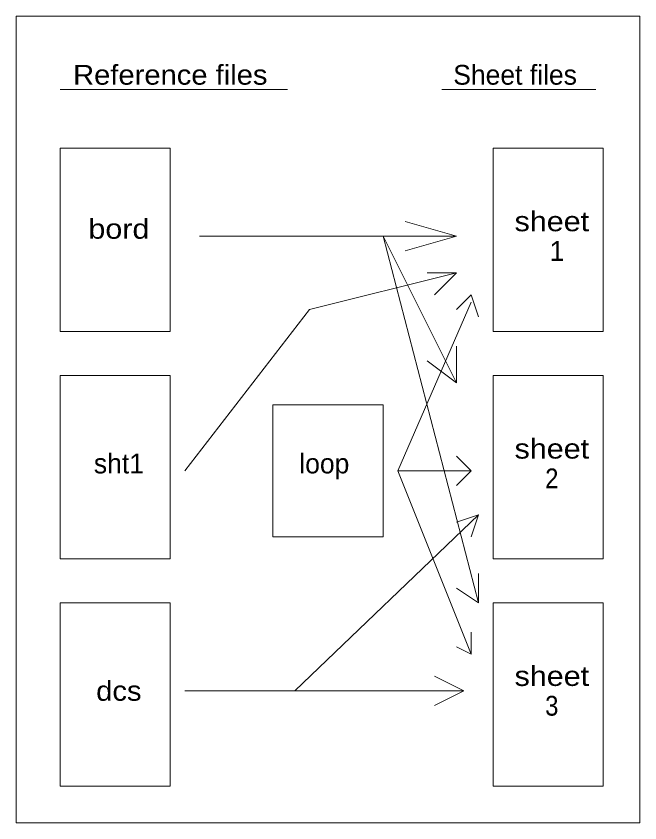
# Model space of a CAD drawing. Extents: x 0 to 0.708, y 0 to 0.917.
import ezdxf
from ezdxf.enums import TextEntityAlignment as Align

# ---------------------------------------------------------------- set-up
doc = ezdxf.new("R2010")
doc.units = 0
doc.header["$LTSCALE"] = 0.009
for name, color, linetype, lineweight in [('30', 7, 'Continuous', 13), ('31', 7, 'Continuous', 13), ('61', 7, 'Continuous', 13), ('62', 7, 'Continuous', 13)]:
    doc.layers.add(name, color=color, linetype=linetype, lineweight=lineweight)
doc.layers.add('5', color=7, linetype='Continuous')

msp = doc.modelspace()

# ---------------------------------------------------------------- linework, layer by layer
at = {"layer": '30'}
for p, q in [((0.416666, 0.666666), (0.5, 0.5)), ((0.416666, 0.666666), (0.525, 0.25)), ((0.433333, 0.4), (0.516666, 0.591666)), ((0.433333, 0.4), (0.516666, 0.4)), ((0.433333, 0.4), (0.516666, 0.191666)), ((0.316666, 0.15), (0.508333, 0.15))]:
    msp.add_line(p, q, dxfattribs=at)
for points in [[(0.208333, 0.666666), (0.416666, 0.666666), (0.5, 0.666666)], [(0.191666, 0.4), (0.333333, 0.583333), (0.5, 0.625)], [(0.191666, 0.15), (0.316666, 0.15), (0.525, 0.35)]]:
    msp.add_lwpolyline(points, dxfattribs=at)
at = {"layer": '31'}
for p, q in [((0.5, 0.666666), (0.441666, 0.683333)), ((0.5, 0.666666), (0.441666, 0.65)), ((0.5, 0.625), (0.466666, 0.625)), ((0.5, 0.625), (0.475, 0.6)), ((0.516666, 0.6), (0.5, 0.583333)), ((0.516666, 0.6), (0.525, 0.575)), ((0.5, 0.5), (0.5, 0.541666)), ((0.5, 0.5), (0.466666, 0.525)), ((0.516666, 0.4), (0.5, 0.416666)), ((0.516666, 0.4), (0.5, 0.383333)), ((0.525, 0.35), (0.5, 0.341666)), ((0.525, 0.35), (0.516666, 0.325)), ((0.525, 0.25), (0.525, 0.283333)), ((0.525, 0.25), (0.5, 0.266666)), ((0.516666, 0.191666), (0.516666, 0.216666)), ((0.516666, 0.191666), (0.5, 0.2)), ((0.508333, 0.15), (0.475, 0.166666)), ((0.508333, 0.15), (0.475, 0.133333))]:
    msp.add_line(p, q, dxfattribs=at)
for points in [[(0.175, 0.766666), (0.05, 0.766666), (0.05, 0.558333), (0.175, 0.558333)], [(0.666666, 0.766666), (0.541666, 0.766666), (0.541666, 0.558333), (0.666666, 0.558333)], [(0.175, 0.508333), (0.05, 0.508333), (0.05, 0.3), (0.175, 0.3)], [(0.666666, 0.508333), (0.541666, 0.508333), (0.541666, 0.3), (0.666666, 0.3)], [(0.291666, 0.325), (0.416666, 0.325), (0.416666, 0.475), (0.291666, 0.475)], [(0.175, 0.25), (0.05, 0.25), (0.05, 0.041666), (0.175, 0.041666)], [(0.666666, 0.25), (0.541666, 0.25), (0.541666, 0.041666), (0.666666, 0.041666)]]:
    msp.add_lwpolyline(points, close=True, dxfattribs=at)
at = {"layer": '61'}
for p, q in [((0, 0), (0, 0.916666)), ((0, 0.916666), (0.708333, 0.916666)), ((0.708333, 0), (0.708333, 0.916666)), ((0, 0), (0.708333, 0))]:
    msp.add_line(p, q, dxfattribs=at)
at = {"layer": '62'}
for p, q in [((0.05, 0.833333), (0.308333, 0.833333)), ((0.483333, 0.833333), (0.658333, 0.833333))]:
    msp.add_line(p, q, dxfattribs=at)

# ---------------------------------------------------------------- texts
at = {"layer": '5'}
for s, width, p in [('sheet', 1.15, (0.608375, 0.67225)), ('bord', 1.15, (0.116708, 0.66375)), ('sheet', 1.15, (0.608375, 0.413916)), ('2', 0.9, (0.608333, 0.380166)), ('sheet', 1.15, (0.608375, 0.155583)), ('dcs', 1.1, (0.116666, 0.13875)), ('3', 0.9, (0.608333, 0.121833))]:
    msp.add_text(s, height=0.0225, dxfattribs=dict(at, width=width)).set_placement(p, align=Align.CENTER)
for s, p in [('1', (0.614106, 0.6385)), ('sht1', (0.116708, 0.397083)), ('loop', (0.35, 0.397083))]:
    msp.add_text(s, height=0.0225, dxfattribs=at).set_placement(p, align=Align.CENTER)
at = {"layer": '62', "width": 1.1}
msp.add_text('Reference files', height=0.0225, dxfattribs=at).set_placement((0.175041, 0.83875), align=Align.CENTER)
at = {"layer": '62'}
msp.add_text('Sheet files', height=0.0225, dxfattribs=at).set_placement((0.566625, 0.83875), align=Align.CENTER)

doc.saveas('drawing.dxf')
